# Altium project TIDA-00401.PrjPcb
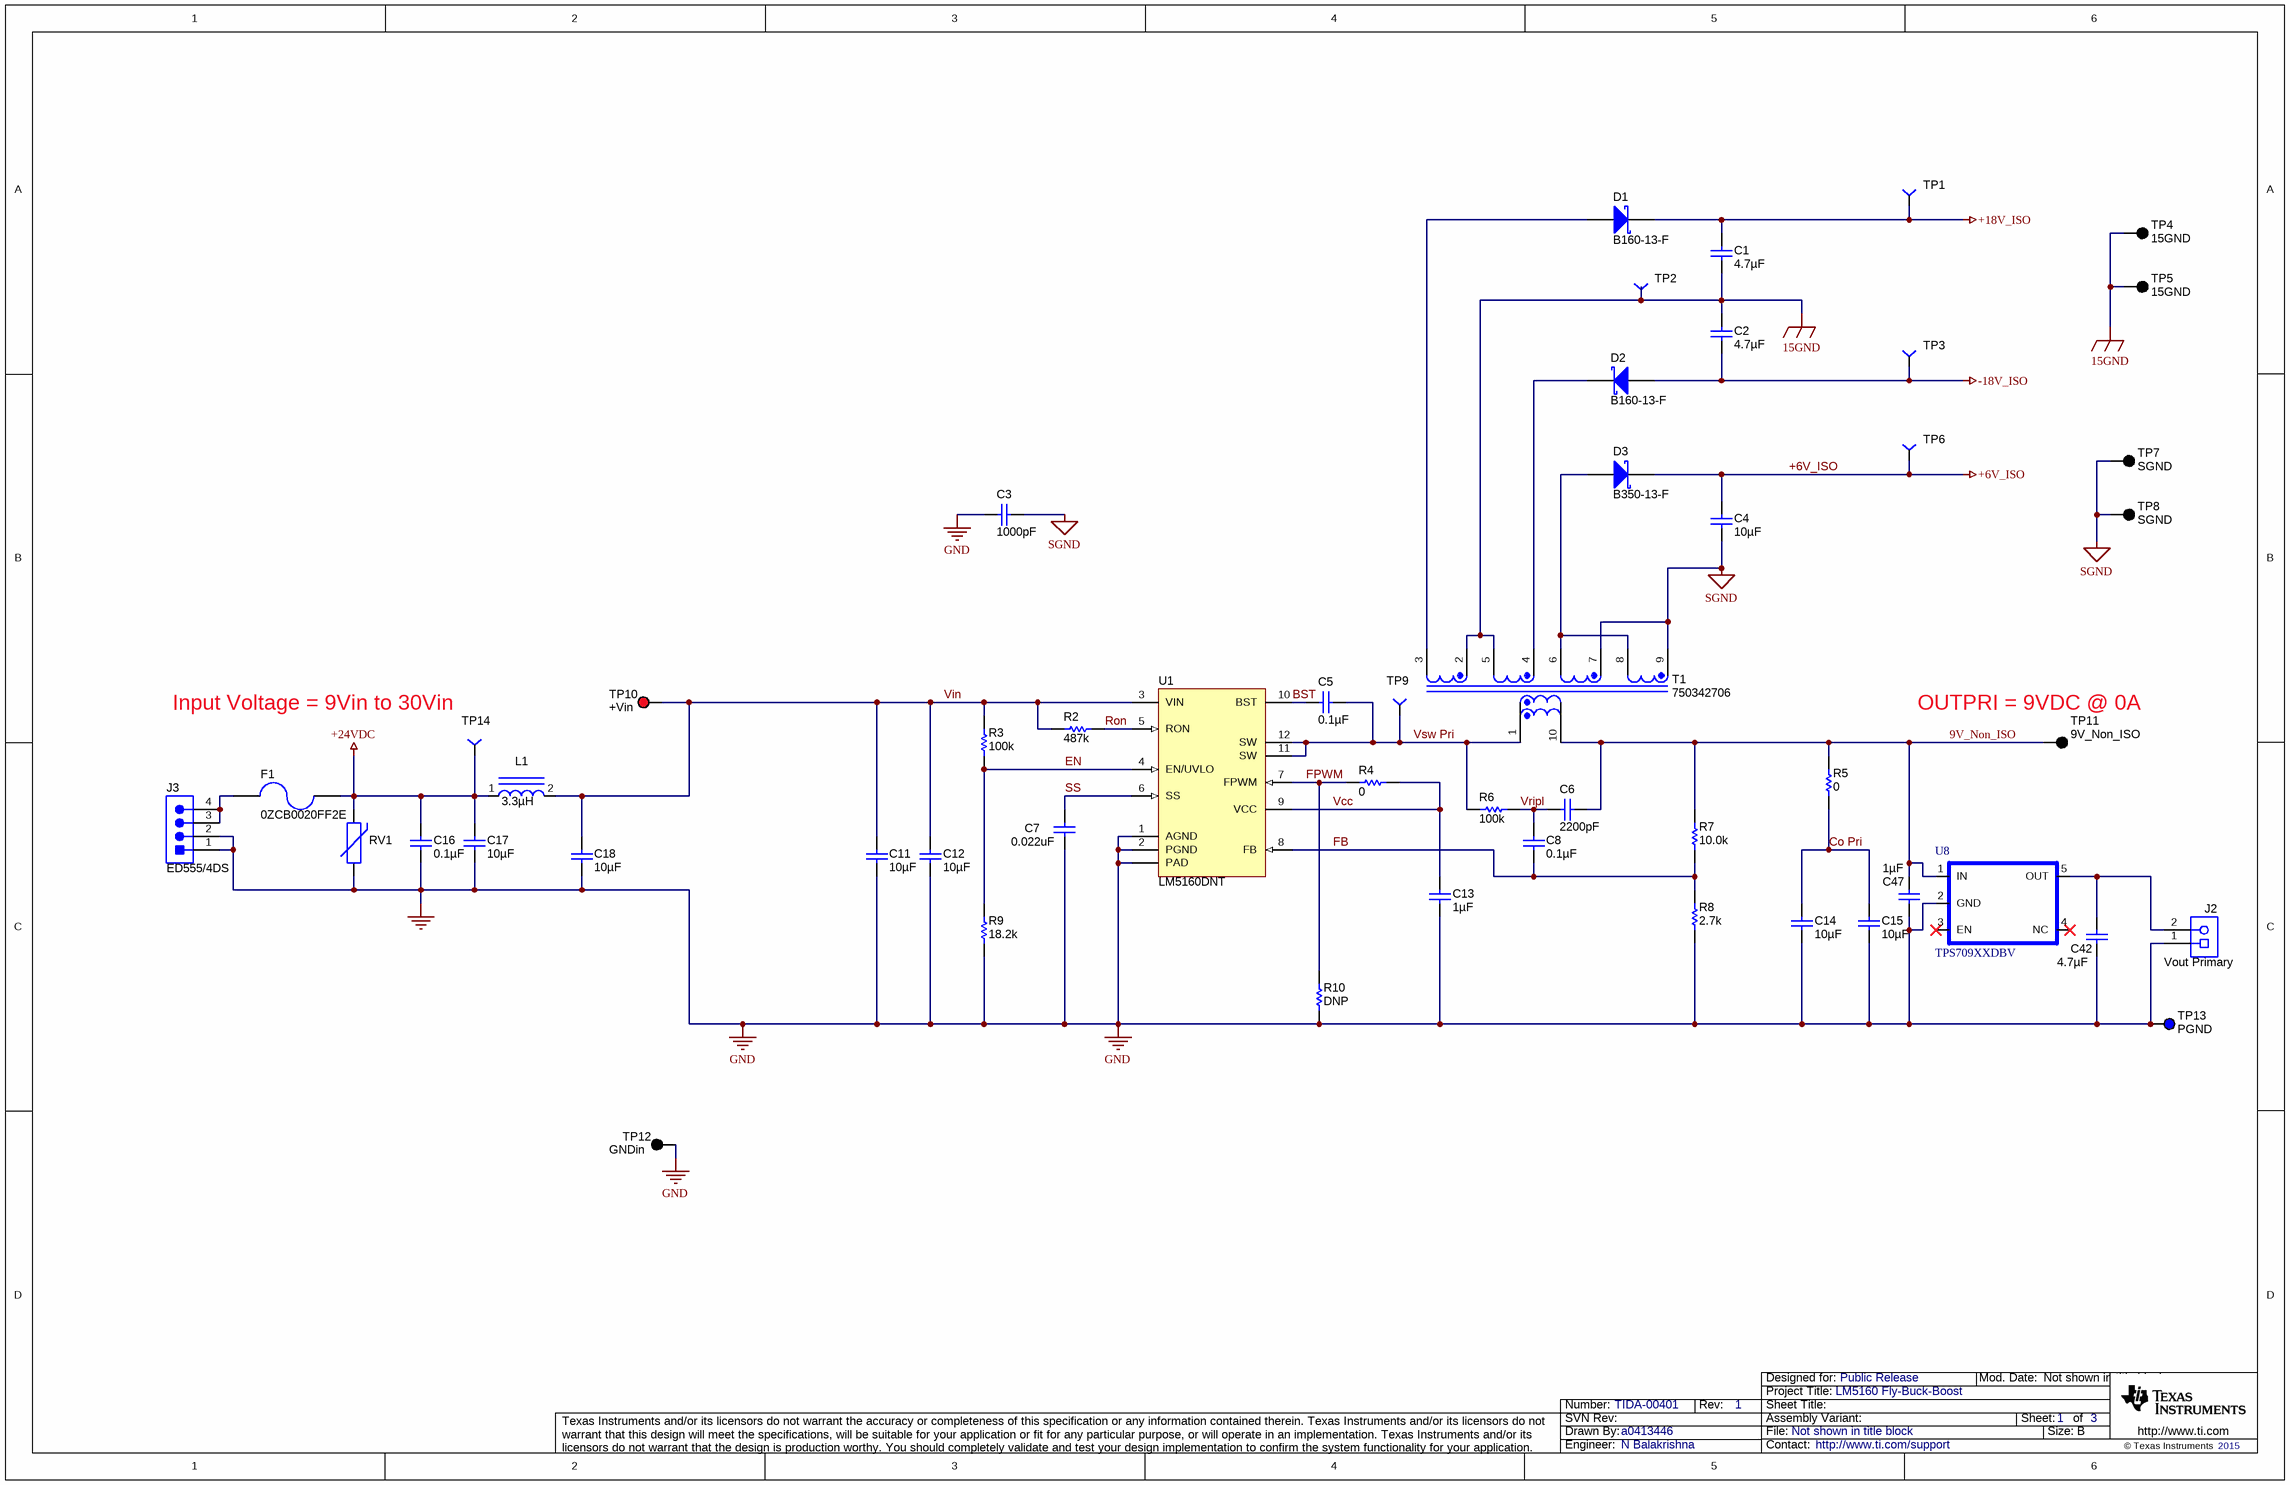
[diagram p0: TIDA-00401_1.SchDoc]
TechSupport: http://www.ti.com/support; SCH_Rev: 1; PRJ_Title: LM5160 Fly-Buck-Boost; PRJ_Number: TIDA-00401; PRJ_Engineer: N Balakrishna; PRJ_Customer: Public Release; PCB_Layout: Manjunatha T N; CopyrightYear: 2015
3 sheets, 133 parts. Net scope: global (net labels, ports and power ports of the same name join across sheets).
Board file: TIDA-00401.PcbDoc
Sheets:
  TIDA-00401_1.SchDoc
  TIDA-00401_LDO_1.SchDoc
  TIDA-00401_HW_1.SchDoc

## Sheet TIDA-00401_1.SchDoc
size 431 x 279 mm; Date: Not shown in title block; ApprovedBy: Not shown in title block; CheckedBy: Not shown in title block; Author: Not shown in title block; CompanyName: Not shown in title block; DrawnBy: a0413446; Engineer: Not shown in title block; Organization: Not shown in title block; Address1: Not shown in title block; Address2: Not shown in title block; Address3: Not shown in title block; Address4: Not shown in title block; DocumentNumber: 1; Revision: Use project parameter SCH_Rev; SheetNumber: 1; SheetTotal: 3; PageSetup: Record=PageOptions¦CenterHorizontal=True¦CenterVertical=True¦PrintScale=0.61¦XCorrection=1.00¦YCorrection=1.00¦PrintKind=0¦BorderSize=5000000¦LeftOffset=0¦BottomOffset=0¦Orientation=2¦PaperLength=1000¦PaperWidth=1000¦Scale=100¦PaperSource=15¦PrintQuality=600¦MediaType=1¦DitherType=10¦PaperKind=Letter¦PrintScaleMode=1

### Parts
C1  ValueDisplayed: 4.7µF  [1206]  (hidden comment: GRM31CR71H475KA12L)
C2  ValueDisplayed: 4.7µF  [1206]  (hidden comment: GRM31CR71H475KA12L)
C3  ValueDisplayed: 1000pF  [1206]  (hidden comment: VJ1206A102JXGAT5Z)
C4  ValueDisplayed: 10µF  [0805_HV]  (hidden comment: EMK212BJ106KG-T)
C5  ValueDisplayed: 0.1µF  [0603]  (hidden comment: C0603C104J3RAC)
C6  ValueDisplayed: 2200pF  [0603]  (hidden comment: C0603C222K5RAC)
C7  ValueDisplayed: 0.022uF  [0603]  (hidden comment: GRM188R71C223KA01D)
C8  ValueDisplayed: 0.1µF  [0603]  (hidden comment: C0603C104J3RAC)
C11  ValueDisplayed: 10µF  [1210]  (hidden comment: GRM32ER71H106KA12L)
C12  ValueDisplayed: 10µF  [1210]  (hidden comment: GRM32ER71H106KA12L)
C13  ValueDisplayed: 1µF  [0603]  (hidden comment: GRM188R71E105KA12D)
C14  ValueDisplayed: 10µF  [0805_HV]  (hidden comment: EMK212BJ106KG-T)
C15  ValueDisplayed: 10µF  [0805_HV]  (hidden comment: EMK212BJ106KG-T)
C16  ValueDisplayed: 0.1µF  [0805]  (hidden comment: C0805C104K1RACTU)
C17  ValueDisplayed: 10µF  [1210]  (hidden comment: GRM32ER71H106KA12L)
C18  ValueDisplayed: 10µF  [1210]  (hidden comment: GRM32ER71H106KA12L)
C42  ValueDisplayed: 4.7µF  [1206]  (hidden comment: GRM31CR71H475KA12L)
C47  ValueDisplayed: 1µF  [0603]  (hidden comment: EMK107B7105KA-T)
D1  B160-13-F  [SMA]
D2  B160-13-F  [SMA]
D3  B350-13-F  [SMC]
F1  0ZCB0020FF2E  [1210]
J2  Vout Primary  [PhoenixConact_1727010]
J3  ED555/4DS  [TERM_BLK_ED555-4DS]
L1  3.3µH  [IND_B82422H]
R2  value 487k  [0603]  (hidden comment: CRCW0603487KFKEA)
R3  ValueDisplayed: 100k  [0603]  (hidden comment: CRCW0603100KFKEA)
R4  ValueDisplayed: 0  [0603]  (hidden comment: CRCW06030000Z0EA)
R5  ValueDisplayed: 0  [0805_HV]  (hidden comment: CRCW08050000Z0EA)
R6  value 100k  [0603]  (hidden comment: CRCW0603100KFKEA)
R7  value 10.0k  [0603]  (hidden comment: CRCW060310K0FKEA)
R8  ValueDisplayed: 2.7k  [0603]  (hidden comment: CRCW06032K70JNEA)
R9  value 18.2k  [0603]  (hidden comment: CRCW060318K2FKEA)
R10  ValueDisplayed: DNP  [0603]  (hidden comment: CRCW06030000Z0EA)
RV1  VC080530A650DP  [1206]  (value not drawn)
T1  750342706  [TR_750342706]
TP1  TP1_PD40_D0.5_S50  [TP1_PD40_D0.5_S50]  (value not drawn)
TP2  TP1_PD40_D0.5_S50  [TP1_PD40_D0.5_S50]  (value not drawn)
TP3  TP1_PD40_D0.5_S50  [TP1_PD40_D0.5_S50]  (value not drawn)
TP4  15GND  [Keystone5011]
TP5  15GND  [Keystone5011]
TP6  TP1_PD40_D0.5_S50  [TP1_PD40_D0.5_S50]  (value not drawn)
TP7  SGND  [Keystone5011]
TP8  SGND  [Keystone5011]
TP9  TP1_PD40_D0.5_S50  [TP1_PD40_D0.5_S50]  (value not drawn)
TP10  +Vin  [Keystone5010]
TP11  9V_Non_ISO  [Keystone5011]
TP12  GNDin  [Keystone5011]
TP13  PGND  [Keystone5127]
TP14  TP1_PD40_D0.5_S50  [TP1_PD40_D0.5_S50]  (value not drawn)
U1  LM5160DNT  [DNT0012B]
U8  TPS709XXDBV  [DBV-5]

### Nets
15GND: C1.1 C2.1 T1.2 T1.5 TP2.1 TP4.1 TP5.1
+6V_ISO: C4.1 D3.1(K) TP6.1
+18V_ISO: C1.2 D1.1(K) TP1.1
+24VDC: C16.1 C17.1 F1.1 L1.1 RV1.2 TP14.1
-18V_ISO: C2.2 D2.2(A) TP3.1
GND: C3.2 C7.2 C11.2 C12.2 C13.2 C14.2 C15.2 C16.2 C17.2 C18.2 C42.1 C47.2 J2.1 J3.1 J3.2 R8.1 R9.1 R10.1 RV1.1 TP12.1 TP13.1 U1.1(AGND) U1.2(PGND) U1.13(PAD) U8.2(GND)
SGND: C3.1 C4.2 T1.7 T1.9 TP7.1 TP8.1
9V_Non_ISO: C6.2 C47.1 R5.2 R7.2 T1.10 TP11.1 U8.1(IN)
BST: C5.2 U1.10(BST)
Co Pri: C14.1 C15.1 R5.1
EN: R3.1 R9.2 U1.4(EN/UVLO)
FB: C8.2 R7.1 R8.2 U1.8(FB)
FPWM: R4.2 R10.2 U1.7(FPWM)
Ron: R2.1 U1.5(RON)
SS: C7.1 U1.6(SS)
Vcc: C13.1 R4.1 U1.9(VCC)
Vin: C11.1 C12.1 C18.1 L1.2 R2.2 R3.2 TP10.1 U1.3(VIN)
Vripl: C6.1 C8.1 R6.2
Vsw Pri: C5.1 R6.1 T1.1 TP9.1 U1.11(SW) U1.12(SW)
NetC42_2: C42.2 J2.2 U8.5(OUT)
NetD1_2: D1.2(A) T1.3
NetD2_1: D2.1(K) T1.4
NetD3_2: D3.2(A) T1.6 T1.8
NetF1_2: F1.2 J3.3 J3.4

Not connected (* = marked no-connect by the designer): U8 3(EN)* 4(NC)*

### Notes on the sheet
- (near TP14) Input Voltage = 9Vin to 30Vin
- (near TP11) OUTPRI = 9VDC @ 0A

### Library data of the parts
C1 C2 C42 = GRM31CR71H475KA12L: CAP, CERM, 4.7uF, 50V, +/-10%, X7R, 1206; Manufacturer: MuRata; Polarized: N; CompType: Capacitor; U/M: EA; Cap_F: 0.0000047; Tolerance_%: 10; Value1: Unknown; VDC_V: 50; TaMin_C: -55; TaMax_C: 125; Cap_Case: 2220
C3 = VJ1206A102JXGAT5Z: CAP, CERM, 1000pF, 1000V, +/-5%, C0G/NP0, 1206; Manufacturer: Vishay-Vitramon; Polarized: N; CompType: Capacitor; U/M: EA; Cap_F: 0.000000001; Tolerance_%: 5; Value1: Unknown; VDC_V: 1000; TaMin_C: -55; TaMax_C: 125
C4 C14 C15 = EMK212BJ106KG-T: CAP, CERM, 10uF, 16V, +/-10%, X5R, 0805; Manufacturer: Taiyo Yuden; Polarized: N; CompType: Capacitor; U/M: EA; Cap_F: 0.00001; Tolerance_%: 10; Value1: Unknown; VDC_V: 16; TaMin_C: -55; TaMax_C: 85; Cap_Case: 0805
C5 C8 = C0603C104J3RAC: CAP, CERM, 0.1uF, 25V, +/-5%, X7R, 0603; Manufacturer: Kemet; Polarized: N; CompType: Capacitor; U/M: EA; Cap_F: 0.0000001; Tolerance_%: 5; Value1: Unknown; VDC_V: 25; TaMin_C: -55; TaMax_C: 125
C6 = C0603C222K5RAC: CAP, CERM, 2200pF, 50V, +/-10%, X7R, 0603; Manufacturer: Kemet; Polarized: N; CompType: Capacitor; U/M: EA; Cap_F: 0.0000000022; Tolerance_%: 10; Value1: Unknown; VDC_V: 50; TaMin_C: -55; TaMax_C: 125
C7 = GRM188R71C223KA01D: CAP, CERM, 0.022uF, 16V, +/-10%, X7R, 0603; Manufacturer: MuRata; Polarized: N; CompType: Capacitor; U/M: EA; Cap_F: 0.000000022; Tolerance_%: 10; Value1: Unknown; VDC_V: 16; TaMin_C: -55; TaMax_C: 125
C11 C12 C17 C18 = GRM32ER71H106KA12L: CAP, CERM, 10uF, 50V, +/-10%, X7R, 1210; Manufacturer: MuRata; Polarized: N; CompType: Capacitor; U/M: EA; Cap_F: 0.00001; Tolerance_%: 10; Value1: Unknown; VDC_V: 50; TaMin_C: -55; TaMax_C: 125
C13 = GRM188R71E105KA12D: CAP, CERM, 1uF, 25V, +/-10%, X7R, 0603; Manufacturer: MuRata; Polarized: N; CompType: Capacitor; U/M: EA; Cap_F: 0.000001; Tolerance_%: 10; Value1: Unknown; VDC_V: 25; TaMin_C: -55; TaMax_C: 125
C16 = C0805C104K1RACTU: CAP, CERM, 0.1uF, 100V, +/-10%, X7R, 0805; Manufacturer: Kemet; Polarized: N; CompType: Capacitor; U/M: EA; Cap_F: 0.0000001; Tolerance_%: 10; ESR_Ohm: 0.064; Value1: 0.064 ohm; VDC_V: 100; IRMS_A: 1.64; TaMin_C: -55; TaMax_C: 125
C47 = EMK107B7105KA-T: CAP, CERM, 1 µF, 16 V, +/- 10%, X7R, 0603; Manufacturer: Taiyo Yuden; Polarized: N; CompType: Capacitor; Value: 1uF; U/M: EA; Cap_F: 0.000001; Tolerance_%: 10; Value1: Unknown; VDC_V: 16; Value2: 16V; TaMin_C: -55; TaMax_C: 85
D1 D2 = B160-13-F: Diode, Schottky, 60 V, 1 A, SMA; Manufacturer: Diodes Inc.; U/M: EA; Vf_V: 0.7; Value: 60V; Value1: 1A; Value2: 0.7V; Io_A: 1; Vr_V: 60; TJmax_C: 150; RJC_CperW: 20
D3 = B350-13-F: Diode, Schottky, 50 V, 3 A, SMC; Manufacturer: Diodes Inc.; U/M: EA; Vf_V: 0.7; Value: 50V; Value1: 3A; Value2: 0.7V; Io_A: 3; Vr_V: 50; TJmax_C: 125; RJC_CperW: 20
F1 = 37215000001: PTC RESTTBLE 0.05A 60V CHIP 1210; Manufacturer: Bel Fuse Inc; CompType: Fuse; U/M: EA; OpeningTime_100%_min: 4; OpeningTime_200%_max: 2; VDC_V: 60; Irating_A: 5; MeltingTyp: 94; Vdrop: 0.08; Soldering_Wave_MaxTemp_C: 260
J2 = 1727010: Conn Term Block, 2POS, 3.81mm, TH; Manufacturer: Phoenix Contact; SymbolCreator: a0412235; Value: 2x1; CompType: Terminal Block; U/M: EA
J3 = ED555/4DS: Terminal Block, 6A, 3.5mm Pitch, 4-Pos, TH; Manufacturer: On-Shore Technology; SymbolCreator: a0412235; CompType: Connector; U/M: EA
L1 = IND_ELJEA_SERIES: Inductor, Chip, ±10%; Manufacturer: EPCOS INC.; PartNumber: B82422H1332K; Area: 28000
R2 = CRCW0603487KFKEA: RES, 487k ohm, 1%, 0.1W, 0603; Manufacturer: Vishay-Dale; CompType: Resistor; Res_ohm: 487000; Tolerance_%: 1; Power_W: 0.1; VDC_V: 75; TempCo: 100 ppm/C; EIA_Code: E96; U/M: EA
R3 = CRCW0603100KFKEA: RES, 100 k, 1%, 0.1 W, 0603; Manufacturer: Vishay-Dale; CompType: Resistor; Value: 100k; Res_ohm: 100000; Tolerance_%: 1; Power_W: 0.1; Value2: 0.1W; VDC_V: 75; TempCo: 100 ppm/C; EIA_Code: E96; U/M: EA
R4 = CRCW06030000Z0EA: RES, 0, 5%, 0.1 W, 0603; Manufacturer: Vishay-Dale; CompType: Resistor; Value: 0; Value_Code: 0000; Tolerance_%: 5; Power_W: 0.1; Value2: 0.1W; VDC_V: 75; TempCo: 200 ppm/C; EIA_Code: E24; U/M: EA
R5 = CRCW08050000Z0EA: RES, 0, 5%, 0.125 W, 0805; Manufacturer: Vishay-Dale; CompType: Resistor; Value: 0; Value_Code: 0000; Tolerance_%: 5; Power_W: 0.125; Value2: 0.125W; VDC_V: 150; TempCo: 200 ppm/C; EIA_Code: E24; U/M: EA
R6 = CRCW0603100KFKEA: RES, 100k ohm, 1%, 0.1W, 0603; Manufacturer: Vishay-Dale; CompType: Resistor; U/M: EA; Res_ohm: 100000; Tolerance_%: 1; Power_W: 0.1; VDC_V: 75; TempCo: 100 ppm/C; EIA_Code: E96
R7 = CRCW060310K0FKEA: RES, 10.0k ohm, 1%, 0.1W, 0603; Manufacturer: Vishay-Dale; CompType: Resistor; U/M: EA; Res_ohm: 10000; Value_Code: 10k0; Tolerance_%: 1; Power_W: 0.1; VDC_V: 75; TempCo: 100 ppm/C; EIA_Code: E96
R8 = CRCW06032K70JNEA: RES, 2.7 k, 5%, 0.1 W, 0603; Manufacturer: Vishay-Dale; CompType: Resistor; Value: 2.7k; Res_ohm: 2700; Value_Code: 2k70; Tolerance_%: 5; Power_W: 0.1; Value2: 0.1W; VDC_V: 75; TempCo: 200 ppm/C; EIA_Code: E24; U/M: EA
R9 = CRCW060318K2FKEA: RES, 18.2k ohm, 1%, 0.1W, 0603; Manufacturer: Vishay-Dale; CompType: Resistor; Res_ohm: 18200; Value_Code: 18k2; Tolerance_%: 1; Power_W: 0.1; VDC_V: 75; TempCo: 100 ppm/C; EIA_Code: E96; U/M: EA
R10 = CRCW06030000Z0EA: RES, 0, 5%, 0.1 W, 0603; Manufacturer: Vishay-Dale; CompType: Resistor; Value: DNP; Res_ohm: 0; Value_Code: 0000; Tolerance_%: 5; Power_W: 0.1; Value2: 0.1W; VDC_V: 75; TempCo: 200 ppm/C; EIA_Code: E24; U/M: EA
RV1 = VC120648D101DP: VARISTOR 36.9V 30A 0805; Manufacturer: AVX; SymbolCreator: a0412235
T1 = 750342178: Transformer, 50 uH, SMT; Manufacturer: Wurth Elektronik eiSos; SymbolCreator: a0799628; Value: 15uH; LeakageL: TBDnH; U/M: EA
TP1-TP3 TP6 TP9 TP14 = TP-040_RND: Test Point 40mil pad 20mil drill; Manufacturer: STD; Value: STD
TP4 TP5 TP7 TP8 TP11 TP12 = 5011: Test Point, Multipurpose, Black, TH; Manufacturer: Keystone; CompType: Test Point Loop; U/M: EA
TP10 = 5010: Test Point, Multipurpose, Red, TH; Manufacturer: Keystone; CompType: Test Point Loop; U/M: EA
TP13 = 5127: Test Point, Multipurpose, Blue, TH; Manufacturer: Keystone; CompType: Test Point Loop; U/M: EA
U1 = LM5160DNT: Wide Input 65V, 1.5A Synchronous Step-Down DC-DC Converter, DNT0012B; Manufacturer: Texas Instruments; Alternate Manufacturer: None; SymbolCreator: a0411947; CompType: IC; U/M: EA
U8 = TPS709XXDBV: IC,150mA, Ultra Low IQ, 1uA LDO Regulator with Enable; Manufacturer: TI; Alternate Manufacturer: None; AREA: 18.50 mm

## Sheet TIDA-00401_LDO_1.SchDoc
size 431 x 279 mm; Date: Not shown in title block; ApprovedBy: Not shown in title block; CheckedBy: Not shown in title block; Author: Not shown in title block; CompanyName: Not shown in title block; Engineer: Not shown in title block; Organization: Not shown in title block; Address1: Not shown in title block; Address2: Not shown in title block; Address3: Not shown in title block; Address4: Not shown in title block; DocumentNumber: 2; Revision: Use project parameter SCH_Rev; SheetNumber: 2; SheetTotal: 3; PageSetup: Record=PageOptions¦CenterHorizontal=True¦CenterVertical=True¦PrintScale=1.00¦XCorrection=1.00¦YCorrection=1.00¦PrintKind=0¦BorderSize=5000000¦LeftOffset=0¦BottomOffset=0¦Orientation=2¦PaperLength=1000¦PaperWidth=1000¦Scale=100¦PaperSource=15¦PrintQuality=600¦MediaType=1¦DitherType=10¦PaperKind=Letter¦PrintScaleMode=1
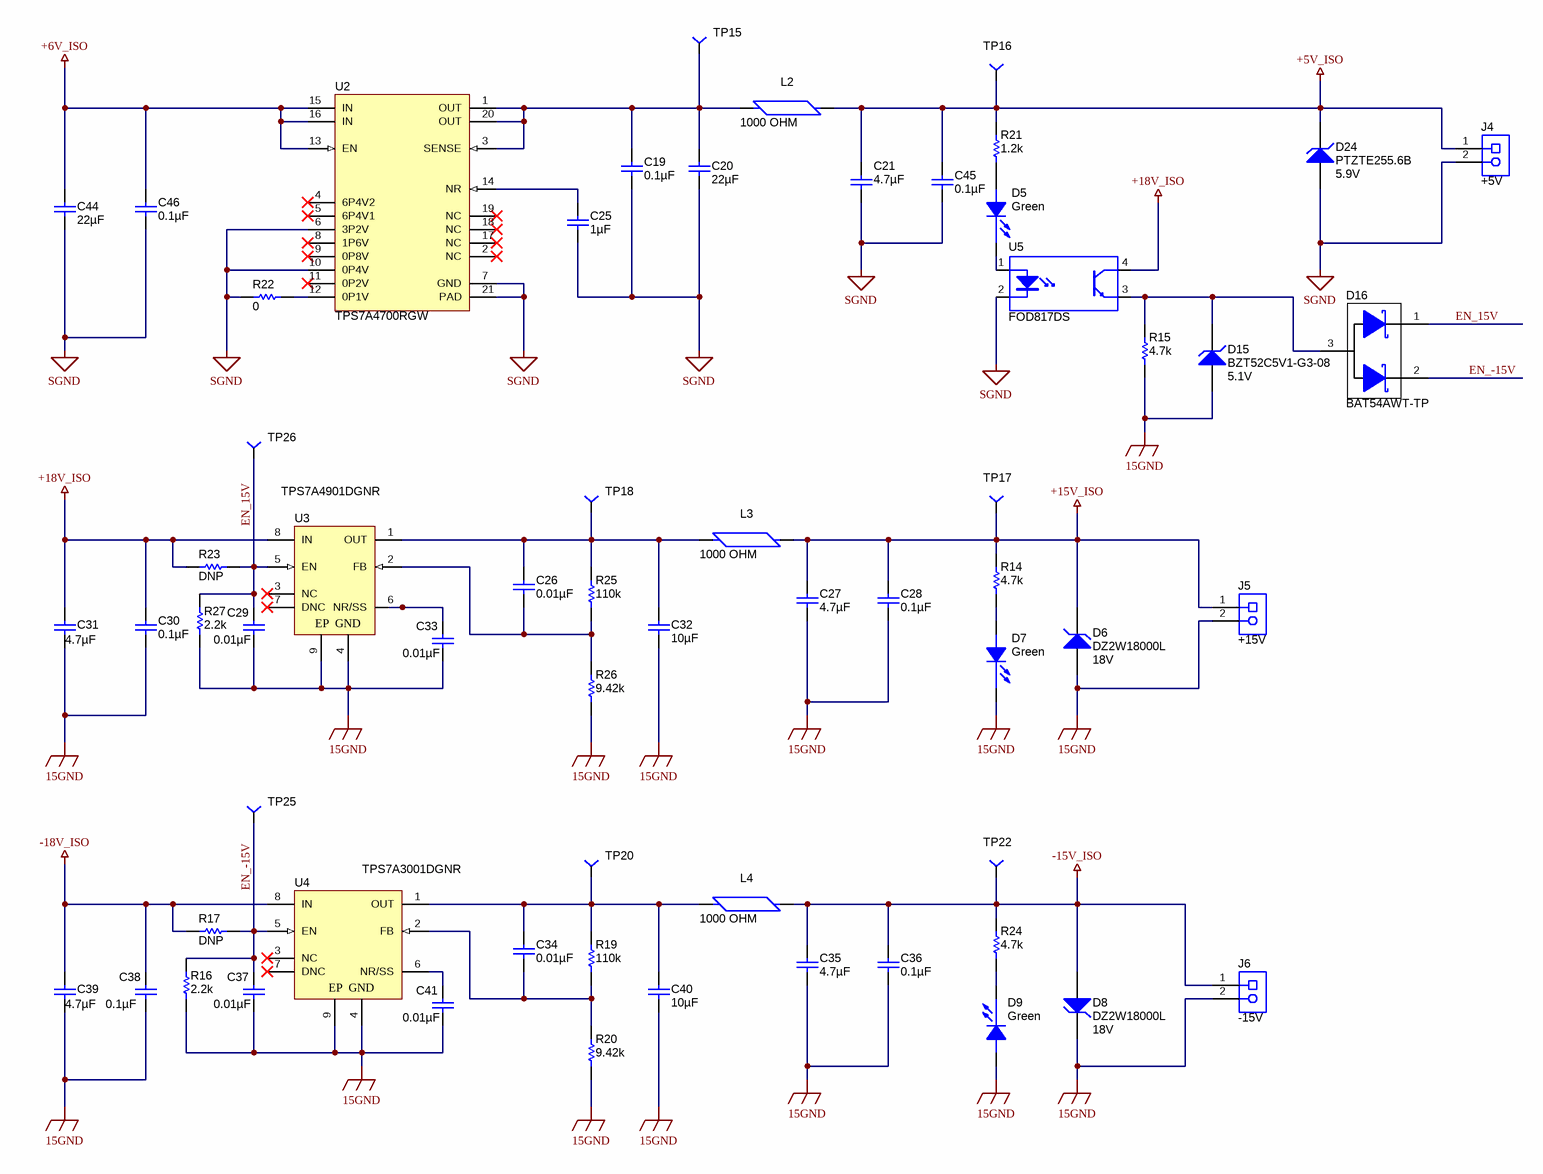
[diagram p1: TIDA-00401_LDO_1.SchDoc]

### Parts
C19  ValueDisplayed: 0.1µF  [0603]  (hidden comment: 06035C104KAT2A)
C20  ValueDisplayed: 22µF  [0805_HV]  (hidden comment: GRM21BR61C226ME44)
C21  ValueDisplayed: 4.7µF  [0805_HV]  (hidden comment: C2012X5R1H475K125AB)
C25  ValueDisplayed: 1µF  [0603]  (hidden comment: C1608X7R1E105K080AB)
C26  ValueDisplayed: 0.01µF  [0603]  (hidden comment: 06031C103JAT2A)
C27  ValueDisplayed: 4.7µF  [0805_HV]  (hidden comment: C2012X5R1H475K125AB)
C28  ValueDisplayed: 0.1µF  [0603]  (hidden comment: 06035C104KAT2A)
C29  ValueDisplayed: 0.01µF  [0603]  (hidden comment: 06031C103JAT2A)
C30  ValueDisplayed: 0.1µF  [0603]  (hidden comment: 06035C104KAT2A)
C31  ValueDisplayed: 4.7µF  [1206]  (hidden comment: GRM31CR71H475KA12L)
C32  ValueDisplayed: 10µF  [1206]  (hidden comment: GRM31CR71E106KA12L)
C33  ValueDisplayed: 0.01µF  [0603]  (hidden comment: 06031C103JAT2A)
C34  ValueDisplayed: 0.01µF  [0603]  (hidden comment: 06031C103JAT2A)
C35  ValueDisplayed: 4.7µF  [0805_HV]  (hidden comment: C2012X5R1H475K125AB)
C36  ValueDisplayed: 0.1µF  [0603]  (hidden comment: 06035C104KAT2A)
C37  ValueDisplayed: 0.01µF  [0603]  (hidden comment: 06031C103JAT2A)
C38  ValueDisplayed: 0.1µF  [0603]  (hidden comment: 06035C104KAT2A)
C39  ValueDisplayed: 4.7µF  [1206]  (hidden comment: GRM31CR71H475KA12L)
C40  ValueDisplayed: 10µF  [1206]  (hidden comment: GRM31CR71E106KA12L)
C41  ValueDisplayed: 0.01µF  [0603]  (hidden comment: 06031C103JAT2A)
C44  ValueDisplayed: 22µF  [0805_HV]  (hidden comment: GRM21BR61C226ME44)
C45  ValueDisplayed: 0.1µF  [0603]  (hidden comment: 06035C104KAT2A)
C46  ValueDisplayed: 0.1µF  [0603]  (hidden comment: 06035C104KAT2A)
D5  value Green  [LED0603AA]  (hidden comment: LED_LG L29K-G2J1-24-Z)
D6  DZ2W18000L  value 18V  [SOD-123]
D7  value Green  [LED0603AA]  (hidden comment: LED_LG L29K-G2J1-24-Z)
D8  DZ2W18000L  value 18V  [SOD-123]
D9  value Green  [LED0603AA]  (hidden comment: LED_LG L29K-G2J1-24-Z)
D15  BZT52C5V1-G3-08  value 5.1V  [SOD-123]
D16  BAT54AWT-TP  [SOT-323]
D24  PTZTE255.6B  value 5.9V  [powerDI123]
J4  +5V  [PhoenixConact_1727010]
J5  +15V  [PhoenixConact_1727010]
J6  -15V  [PhoenixConact_1727010]
L2  1000 OHM  [FB0603]
L3  1000 OHM  [FB0603]
L4  1000 OHM  [FB0603]
R14  value 4.7k  [0603]  (hidden comment: CRCW06034K70JNEA)
R15  value 4.7k  [0603]  (hidden comment: CRCW06034K70JNEA)
R16  ValueDisplayed: 2.2k  [0603]  (hidden comment: CRCW06032K20JNEA)
R17  ValueDisplayed: DNP  [0603]  (hidden comment: CRCW06030000Z0EA)
R19  value 110k  [0603]  (hidden comment: CRCW0402110KFKED)
R20  value 9.42k  [0603]  (hidden comment: TNPW04029K42BEED)
R21  value 1.2k  [0402]  (hidden comment: CRCW04021K20JNED)
R22  ValueDisplayed: 0  [0603]  (hidden comment: CRCW06030000Z0EA)
R23  ValueDisplayed: DNP  [0603]  (hidden comment: CRCW06030000Z0EA)
R24  value 4.7k  [0603]  (hidden comment: CRCW06034K70JNEA)
R25  value 110k  [0603]  (hidden comment: CRCW0402110KFKED)
R26  value 9.42k  [0603]  (hidden comment: TNPW04029K42BEED)
R27  ValueDisplayed: 2.2k  [0603]  (hidden comment: CRCW06032K20JNEA)
TP15  TP1_PD40_D0.5_S50  [TP1_PD40_D0.5_S50]  (value not drawn)
TP16  TP-038  [TP1_PD40_D0.5_S50]  (value not drawn)
TP17  TP-038  [TP1_PD40_D0.5_S50]  (value not drawn)
TP18  TP1_PD40_D0.5_S50  [TP1_PD40_D0.5_S50]  (value not drawn)
TP20  TP1_PD40_D0.5_S50  [TP1_PD40_D0.5_S50]  (value not drawn)
TP22  TP-038  [TP1_PD40_D0.5_S50]  (value not drawn)
TP25  TP1_PD40_D0.5_S50  [TP1_PD40_D0.5_S50]  (value not drawn)
TP26  TP1_PD40_D0.5_S50  [TP1_PD40_D0.5_S50]  (value not drawn)
U2  TPS7A4700RGW  [RGW0020A]
U3  TPS7A4901DGNR  [DGN0008D_N]
U4  TPS7A3001DGNR  [DGN0008D_N]
U5  FOD817DS  [N04C]

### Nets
15GND: C27.1 C28.1 C29.2 C30.1 C31.2 C32.2 C33.2 C35.1 C36.1 C37.2 C38.1 C39.2 C40.2 C41.2 D6.2(A) D7.1(C) D8.1(K) D9.2(A) D15.2(A) J5.2 J6.2 R15.2 R16.1 R20.2 R26.2 R27.1 U3.4(GND) U3.9(EP) U4.4(GND) U4.9(EP)
+5V_ISO: C21.1 C45.2 D24.1(K) J4.1 L2.2 R21.1 TP16.1
+6V_ISO: C44.1 C46.2 U2.13(EN) U2.15(IN) U2.16(IN)
+15V_ISO: C27.2 C28.2 D6.1(K) J5.1 L3.2 R14.1 TP17.1
+18V_ISO: C30.2 C31.1 R23.2 U3.8(IN) U5.4(C)
-15V_ISO: C35.2 C36.2 D8.2(A) J6.1 L4.2 R24.1 TP22.1
-18V_ISO: C38.2 C39.1 R17.2 U4.8(IN)
SGND: C19.1 C20.2 C21.2 C25.2 C44.2 C45.1 C46.1 D24.2(A) J4.2 R22.2 U2.6(3P2V) U2.7(GND) U2.10(0P4V) U2.21(PAD) U5.2(K)
EN_15V: C29.1 D16.1(A) R23.1 R27.2 TP26.1 U3.5(EN)
EN_-15V: C37.1 D16.2(K) R16.2 R17.1 TP25.1 U4.5(EN)
NetC19_2: C19.2 C20.1 L2.1 TP15.1 U2.1(OUT) U2.3(SENSE) U2.20(OUT)
NetC25_1: C25.1 U2.14(NR)
NetC26_1: C26.1 C32.1 L3.1 R25.1 TP18.1 U3.1(OUT)
NetC26_2: C26.2 R25.2 R26.1 U3.2(FB)
NetC33_1: C33.1 U3.6(NR/SS)
NetC34_1: C34.1 C40.1 L4.1 R19.1 TP20.1 U4.1(OUT)
NetC34_2: C34.2 R19.2 R20.1 U4.2(FB)
NetC41_1: C41.1 U4.6(NR/SS)
NetD5_1: D5.1(C) U5.1(A)
NetD5_2: D5.2(A) R21.2
NetD7_2: D7.2(A) R14.2
NetD9_1: D9.1(C) R24.2
NetD15_1: D15.1(K) D16.3(A) R15.1 U5.3(E)
NetR22_1: R22.1 U2.12(0P1V)

Not connected (* = marked no-connect by the designer): U2 2(NC)* 4(6P4V2)* 5(6P4V1)* 8(1P6V)* 9(0P8V)* 11(0P2V)* 17(NC)* 18(NC)* 19(NC)*; U3 3(NC)* 7(DNC)*; U4 3(NC)* 7(DNC)*

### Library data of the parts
C19 C28 C30 C36 C38 C45 C46 = 06035C104KAT2A: CAP, CERM, 0.1uF, 50V, +/-10%, X7R, 0603; Manufacturer: AVX; Polarized: N; CompType: Capacitor; U/M: EA; Cap_F: 0.0000001; Tolerance_%: 10; Value1: Unknown; VDC_V: 50; TaMin_C: -55; TaMax_C: 125
C20 C44 = GRM21BR61C226ME44: CAP, CERM, 22uF, 16V, +/-20%, X5R, 0805; Manufacturer: MuRata; Polarized: N; CompType: Capacitor; U/M: EA; Cap_F: 0.000022; Tolerance_%: 20; Value1: Unknown; VDC_V: 16; TaMin_C: -55; TaMax_C: 85; Cap_Case: 0805
C21 C27 C35 = C2012X5R1H475K125AB: CAP, CERM, 4.7uF, 50V, +/-10%, X5R, 0805; Manufacturer: TDK; Polarized: N; CompType: Capacitor; U/M: EA; Cap_F: 0.0000047; Tolerance_%: 10; Value1: Unknown; VDC_V: 50; TaMin_C: -55; TaMax_C: 85; Cap_Case: 0805
C25 = C1608X7R1E105K080AB: CAP, CERM, 1uF, 25V, +/-10%, X7R, 0603; Manufacturer: TDK; Polarized: N; CompType: Capacitor; U/M: EA; Cap_F: 0.000001; Tolerance_%: 10; Value1: Unknown; VDC_V: 25; TaMin_C: -55; TaMax_C: 125
C26 C29 C33 C34 C37 C41 = 06031C103JAT2A: CAP, CERM, 0.01uF, 100V, +/-5%, X7R, 0603; Manufacturer: AVX; Polarized: N; CompType: Capacitor; U/M: EA; Cap_F: 0.00000001; Tolerance_%: 5; ESR_Ohm: 0.098; Value1: 0.098 ohm; VDC_V: 100; TaMin_C: -55; TaMax_C: 125
C31 C39 = GRM31CR71H475KA12L: as C1 on sheet TIDA-00401_1
C32 C40 = GRM31CR71E106KA12L: CAP, CERM, 10uF, 25V, +/-10%, X7R, 1206; Manufacturer: MuRata; Polarized: N; CompType: Capacitor; U/M: EA; Cap_F: 0.00001; Tolerance_%: 10; Value1: Unknown; VDC_V: 25; TaMin_C: -55; TaMax_C: 125; Cap_Case: 2220
D5 D7 D9 = LED_LG L29K-G2J1-24-Z: LED SmartLED Green 570NM; Manufacturer: OSRAM; SymbolCreator: x0120606
D6 D8 = DZ2W18000L: Diode, Zener, 18V, 1W, SOD-123; Manufacturer: Panasonic
D15 = BZT52C5V1-G3-08: Diode, Zener, 5.1 V, 500 mW, SOD-123; Manufacturer: Vishay-Semiconductor; SymbolCreator: a0412235; U/M: EA; Power_W: 0.5; Vz_V: 5.1; Value1: 0.5W; RJA_CperW: 300
D16 = BAT54AWT-TP: Diode, Schottky, 30 V, 0.2 A, SOT-323; Manufacturer: Micro Commercial Components; SymbolCreator: a0412235; U/M: EA; Vf_V: 1; Value: 30V; Value1: 0.2A; Value2: 1V; Io_A: 0.2; Vr_V: 30; TJmax_C: 125; RJC_CperW: 500
D24 = PTZTE255.6B: DIODE ZENER 5.9V 1W PMDS; Manufacturer: Rohm Semiconductor; U/M: EA; Vz_V: 5.9
J4-J6 = 1727010: as J2 on sheet TIDA-00401_1
L2 = MMZ1608B102C: FERRITE CHIP 1000 OHM 1500MA 0805; PartNumber: MPZ2012S102AT000; Manufacturer: TDK Corporation; CompType: Ferrite Bead
L3 L4 = MMZ1608B102C: FERRITE CHIP 1000 OHM 300MA 0603; Manufacturer: TDK Corporation; CompType: Ferrite Bead
R14 R15 R24 = CRCW06034K70JNEA: RES, 4.7k ohm, 5%, 0.1W, 0603; Manufacturer: Vishay-Dale; CompType: Resistor; Res_ohm: 4700; Value_Code: 4k70; Tolerance_%: 5; Power_W: 0.1; VDC_V: 75; TempCo: 200 ppm/C; EIA_Code: E24; U/M: EA
R16 R27 = CRCW06032K20JNEA: RES, 2.2 k, 5%, 0.1 W, 0603; Manufacturer: Vishay-Dale; CompType: Resistor; Value: 2.2k; Res_ohm: 2200; Value_Code: 2k20; Tolerance_%: 5; Power_W: 0.1; Value2: 0.1W; VDC_V: 75; TempCo: 200 ppm/C; EIA_Code: E24; U/M: EA
R17 R22 R23 = CRCW06030000Z0EA: as R4 on sheet TIDA-00401_1
R19 R25 = CRCW0402110KFKED: RES, 110k ohm, 1%, 0.063W, 0402; Manufacturer: Vishay-Dale; CompType: Resistor; Res_ohm: 110000; Tolerance_%: 1; Power_W: 0.063; VDC_V: 50; TempCo: 100 ppm/C; EIA_Code: E96; U/M: EA
R20 R26 = CRCW04029K31FKED: RES, 9.42k ohm, 1%, 0.063W, 0402; Manufacturer: Vishay-Dale; CompType: Resistor; Res_ohm: 9310; Value_Code: 9k42; Tolerance_%: 1; Power_W: 0.063; VDC_V: 50; TempCo: 100 ppm/C; EIA_Code: E96; U/M: EA
R21 = CRCW04021K20JNED: RES, 1.2k ohm, 5%, 0.063W, 0402; Manufacturer: Vishay-Dale; CompType: Resistor; Res_ohm: 1200; Value_Code: 1k20; Tolerance_%: 5; Power_W: 0.063; VDC_V: 50; TempCo: 200 ppm/C; EIA_Code: E24; U/M: EA
TP15 TP18 TP20 TP25 TP26 = TP-040_RND: as TP1 on sheet TIDA-00401_1
TP16 TP17 TP22 = TP-038: Test Point 40mil pad 20mil drill; Manufacturer: STD; Value: STD
U2 = TPS7A4700RGW: 36-V, 1-A, 4.17-µVRMS, RF LDO Voltage Regulator, RGW0020A; Manufacturer: Texas Instruments; SymbolCreator: a0412235; CompType: IC; U/M: EA
U3 = TPS7A4901DGNR: Single Output High PSRR LDO, 150 mA, Adjustable 1.2 to 33 V Output, 3 to 36 V Input, with Ultra-Low Noise, 8-pin MSOP (DGN), -40 to 125 degC, Green (RoHS & no Sb/Br); Manufacturer: Texas Instruments; Alternate Manufacturer: None; Alternate PartNumber: Equivalent; Accuracy(%): 1.5; Iout(Max)(A): 0.15; Iq(Typ)(mA): 0.06; Power Good: TRUE; SubFamily: Single Channel LDO; Vdo(Typ)(mV): 260; Vin(Max)(V): 36; Vin(Min)(V): 3; Vout Adj(Max)(V): 33; Vout Adj(Min)(V): 1.2
U4 = TPS7A3001DGNR: Single Output High PSRR LDO, 200 mA, Adjustable -1.18 to -33 V Output, -3 to -36 V Input, with Ultra-Low Noise, 8-pin MSOP (DGN), -40 to 125 degC, Green (RoHS & no Sb/Br); Manufacturer: Texas Instruments; Alternate Manufacturer: None; Alternate PartNumber: Equivalent; Accuracy(%): 1.5; Iout(Max)(A): 0.2; Iq(Typ)(mA): 0.05; SubFamily: Single Channel LDO; Vdo(Typ)(mV): 216
U5 = FOD817DS: Optocoupler, 5kV RMS, SMT; Manufacturer: Fairchild Semiconductor; U/M: EA

## Sheet TIDA-00401_HW_1.SchDoc
size 431 x 279 mm; Date: Not shown in title block; ApprovedBy: Not shown in title block; CheckedBy: Not shown in title block; Author: Not shown in title block; CompanyName: Not shown in title block; Engineer: Not shown in title block; Organization: Not shown in title block; Address1: Not shown in title block; Address2: Not shown in title block; Address3: Not shown in title block; Address4: Not shown in title block; DocumentNumber: 3; Revision: Use project parameter SCH_Rev; SheetNumber: 3; SheetTotal: 3; PageSetup: Record=PageOptions|CenterHorizontal=True|CenterVertical=True|PrintScale=1.00|XCorrection=1.00|YCorrection=1.00|PrintKind=0|BorderSize=5000000|LeftOffset=0|BottomOffset=0|Orientation=2|PaperLength=1000|PaperWidth=1000|Scale=100|PaperSource=15|PrintQuality=600|MediaType=1|DitherType=10|PaperKind=Letter|PrintScaleMode=1
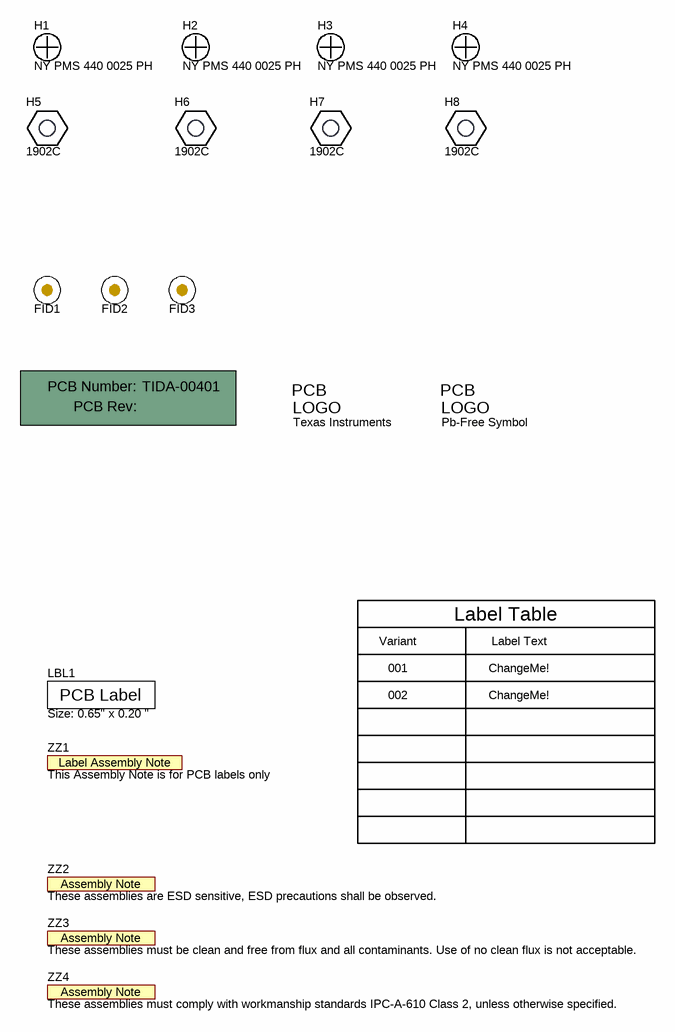
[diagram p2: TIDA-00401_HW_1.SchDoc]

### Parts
!PCB1  Printed Circuit Board  (value not drawn)  (mechanical)
FID1  Fiducial  [Fiducial10-20]  (value not drawn)
FID2  Fiducial  [Fiducial10-20]  (value not drawn)
FID3  Fiducial  [Fiducial10-20]  (value not drawn)
H1  NY PMS 440 0025 PH  [NY PMS 440 0025 PH]
H2  NY PMS 440 0025 PH  [NY PMS 440 0025 PH]
H3  NY PMS 440 0025 PH  [NY PMS 440 0025 PH]
H4  NY PMS 440 0025 PH  [NY PMS 440 0025 PH]
H5  1902C  [Keystone_1902C]
H6  1902C  [Keystone_1902C]
H7  1902C  [Keystone_1902C]
H8  1902C  [Keystone_1902C]
LBL1  Size: 0.65" x 0.20 "  [Label_650x200]
Logo1  Texas Instruments  [TI_Stacked_Overlay_Medium]  (no BOM)
Logo2  Pb-Free Symbol  [Pb-Free_Overlay_Small]  (no BOM)
ZZ1  This Assembly Note is for PCB labels only  [AssemblyNoteLabel]  (no BOM)
ZZ2  These assemblies are ESD sensitive, ESD precautions shall be observed.  [AssemblyNote]  (no BOM)
ZZ3  These assemblies must be clean and free from flux and all contaminants. Use of no clean flux is not acceptable.  [AssemblyNote]  (no BOM)
ZZ4  These assemblies must comply with workmanship standards IPC-A-610 Class 2, unless otherwise specified.  [AssemblyNote]  (no BOM)

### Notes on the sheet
- Variant
- Label Table
- Label Text
- 001
- 002
- ChangeMe!

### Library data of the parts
!PCB1 = PCB: Manufacturer: Any; PartNumber: TIDA-00401; SymbolCreator: a0412235
FID1-FID3 = Fiducial: Fiducial mark.  There is nothing to buy or mount.; SymbolCreator: codlsc
H1-H4 = NY PMS 440 0025 PH: Machine Screw, Round, #4-40 x 1/4, Nylon, Philips panhead; Manufacturer: B&F Fastener Supply; CompType: Hardware; SymbolCreator: codlsc; U/M: EA
H5-H8 = 1902C: Standoff, Hex, 0.5"L #4-40 Nylon; Manufacturer: Keystone; CompType: Hardware; SymbolCreator: a0412235
LBL1 = THT-14-423-10: Thermal Transfer Printable Labels, 0.650" W x 0.200" H - 10,000 per roll; Manufacturer: Brady; SymbolCreator: a0412235; CompType: Label
Logo1 = TI_Logo: Texas Instrument Corporate Signature; SymbolCreator: a0412235
Logo2 = Pb-Free: SymbolCreator: a0412235
ZZ1 = AssemblyNoteLabel: SymbolCreator: a0412235
ZZ2-ZZ4 = AssemblyNote: SymbolCreator: codlsc

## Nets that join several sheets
15GND: TIDA-00401_1 (7 pins), TIDA-00401_LDO_1 (30 pins)
+6V_ISO: TIDA-00401_1 (C4.1 D3.1 TP6.1), TIDA-00401_LDO_1 (5 pins)
+18V_ISO: TIDA-00401_1 (C1.2 D1.1 TP1.1), TIDA-00401_LDO_1 (5 pins)
-18V_ISO: TIDA-00401_1 (C2.2 D2.2 TP3.1), TIDA-00401_LDO_1 (C38.2 C39.1 R17.2 U4.8)
SGND: TIDA-00401_1 (6 pins), TIDA-00401_LDO_1 (15 pins)

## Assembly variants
001: not fitted FID1 FID2 FID3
